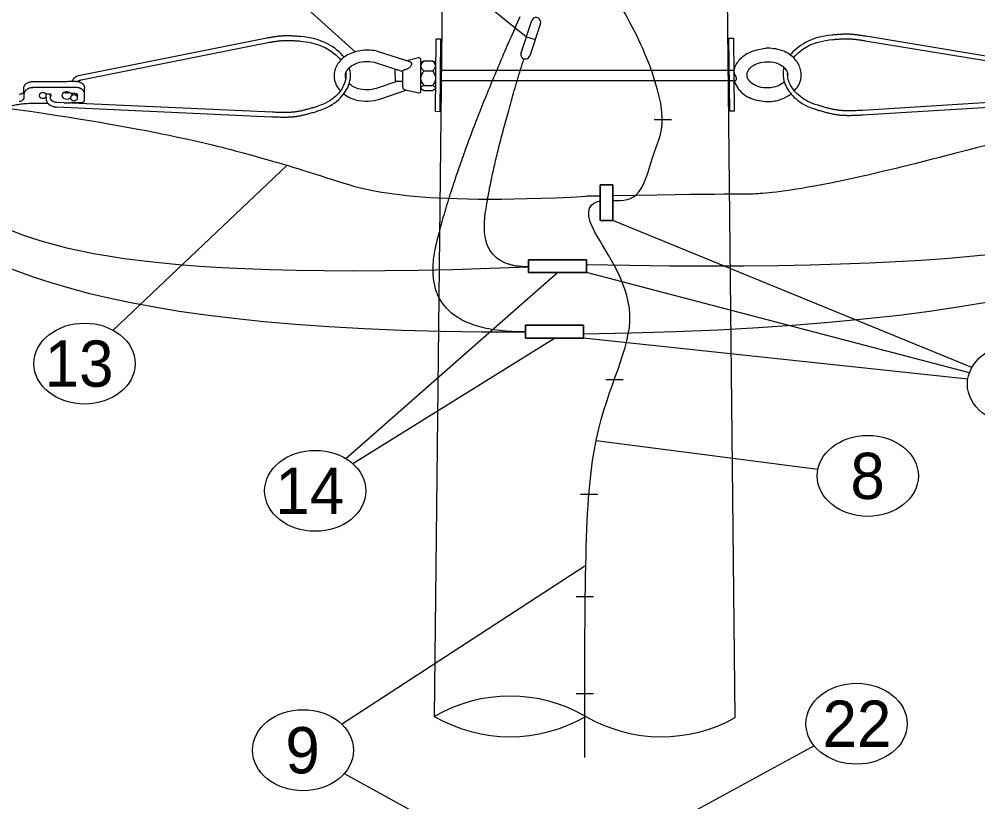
# Model space of a CAD drawing. Extents: x 99862 to 104211, y 98939 to 102076.
# Drawn here: x 101674.9 to 102006.5, y 101094.6 to 101365.3 of the extents above; entities that cross this region are included whole.
import ezdxf

# ---------------------------------------------------------------- set-up
doc = ezdxf.new("R2010")
doc.units = 0
for name, color, linetype in [('Level 1', 7, 'Continuous'), ('Level 11', 7, 'Continuous'), ('Level 12', 7, 'Continuous'), ('Level 13', 7, 'Continuous'), ('Level 15', 7, 'Continuous'), ('Level 16', 7, 'Continuous'), ('Level 17', 7, 'Continuous'), ('Level 20', 7, 'Continuous'), ('Level 40', 7, 'Continuous'), ('Level 5', 7, 'Continuous'), ('Level 6', 7, 'Continuous')]:
    doc.layers.add(name, color=color, linetype=linetype)

msp = doc.modelspace()

# ---------------------------------------------------------------- linework, layer by layer
at = {"layer": 'Level 1'}
for p, q in [((101822.66, 101507.01), (101818.5, 101124.11)), ((101922.64, 101123.74), (101918.48, 101507.01))]:
    msp.add_line(p, q, dxfattribs=at)
for centre, start, end in [((101844.7, 101078.73), 60, 120), ((101844.7, 101169.49), 240, 300), ((101897.1, 101169.49), 240, 299.1652)]:
    msp.add_arc(centre, 52.4, start, end, dxfattribs=at)
at = {"layer": 'Level 11'}
for p, q in [((101894.6, 101330.58), (101900.6, 101330.58)), ((101877.88, 101240.67), (101883.88, 101240.67)), ((101869.05, 101201.02), (101875.05, 101201.02)), ((101867.57, 101165.56), (101873.57, 101165.56)), ((101867.57, 101131.99), (101873.57, 101131.99))]:
    msp.add_line(p, q, dxfattribs=at)
for points, degree in [([(101880.31, 101302.54), (101883.77, 101302.51), (101890.12, 101302.55), (101894.49, 101320.44), (101899.51, 101330.05), (101891.01, 101357.11), (101876.44, 101380.43), (101871.67, 101395.71), (101871.77, 101403.52)], 3), ([(101850, 101257.11), (101811.89, 101257.11), (101826.6, 101318.15), (101848.24, 101366.2)], 2), ([(101851.09, 101279.6), (101833.87, 101279.6), (101838.28, 101315.06), (101849.48, 101351.62)], 2), ([(101870.57, 101109.85), (101870.57, 101176.15), (101870.57, 101226.43), (101894.7, 101263.78), (101867.64, 101297.44), (101872.7, 101301.79), (101875.86, 101302.4)], 3)]:
    msp.add_open_spline(points, degree=degree, dxfattribs=at)
at = {"layer": 'Level 12'}
for points, degree in [([(101664.3, 101335.46), (101718.51, 101328.04), (101761.77, 101316.71), (101778.05, 101311.49), (101811.01, 101300.81), (101871.2, 101304.04)], 3), ([(102062.44, 101335.69), (101998.25, 101318.55), (101954.14, 101307.33), (101926.64, 101304.24), (101926.64, 101304.98), (101880.31, 101304.22)], 3), ([(101875.86, 101304.13), (101874.35, 101304.1), (101872.8, 101304.07), (101871.2, 101304.04)], 2)]:
    msp.add_open_spline(points, degree=degree, dxfattribs=at)
at = {"layer": 'Level 13'}
for p, q in [((101697.5, 101339.42), (101697.47, 101341.54)), ((101681.79, 101338.86), (101681.79, 101338.86)), ((101685.25, 101339.38), (101684.16, 101339.37)), ((101685.28, 101339.38), (101685.25, 101339.38)), ((101689.62, 101338.9), (101689.62, 101338.9)), ((101694.27, 101339.59), (101692.78, 101339.58))]:
    msp.add_line(p, q, dxfattribs=at)
for centre, major_axis, start_param, end_param in [((101683.07, 101338.88), (-1.28, -0.01), 3.682555, 8.848759), ((101691.32, 101338.92), (-1.71, -0.02), 3.682555, 8.831964), ((101691.3, 101341.04), (1.71, 0.02), 4.155415, 5.269363), ((101685.28, 101338.89), (-0.669, -0.008), 2.263509, 4.704116), ((101694.27, 101338.93), (-0.891, -0.01), 2.333521, 4.704116)]:
    msp.add_ellipse(centre, major_axis=major_axis, ratio=0.733102, start_param=start_param, end_param=end_param, dxfattribs=at)
for points, degree in [([(101674.83, 101339.44), (101675.14, 101339.38), (101675.45, 101339.39), (101675.99, 101339.57), (101676.21, 101339.73), (101676.41, 101340.03), (101676.45, 101340.13), (101676.49, 101340.36), (101676.48, 101340.48), (101676.48, 101340.83), (101676.48, 101341.06), (101676.48, 101341.41), (101676.48, 101341.53), (101676.5, 101341.75), (101676.52, 101341.87), (101676.59, 101342.09), (101676.64, 101342.2), (101676.76, 101342.41), (101676.83, 101342.51), (101677.07, 101342.8), (101677.27, 101342.98), (101677.74, 101343.28), (101678.01, 101343.4), (101678.3, 101343.51)], 3), ([(101678.3, 101343.51), (101678.53, 101343.58), (101678.76, 101343.64), (101679.12, 101343.69), (101679.24, 101343.71), (101679.48, 101343.72), (101680.1, 101343.72), (101681.69, 101343.73), (101685.13, 101343.75), (101689.06, 101343.77), (101692.26, 101343.79), (101693.61, 101343.8), (101693.97, 101343.8), (101694.22, 101343.8), (101694.59, 101343.81), (101694.95, 101343.77), (101695.43, 101343.67), (101695.67, 101343.6), (101696.1, 101343.42), (101696.31, 101343.31), (101696.67, 101343.06), (101696.83, 101342.92), (101697.11, 101342.62), (101697.22, 101342.45), (101697.38, 101342.11), (101697.44, 101341.92), (101697.47, 101341.67), (101697.47, 101341.59), (101697.47, 101341.52)], 3), ([(101678.33, 101341.38), (101678.04, 101341.28), (101677.77, 101341.15), (101677.3, 101340.81), (101677.1, 101340.62), (101676.86, 101340.3), (101676.79, 101340.19), (101676.67, 101339.97), (101676.62, 101339.85), (101676.55, 101339.62), (101676.53, 101339.5), (101676.51, 101339.27), (101676.51, 101339.15), (101676.51, 101338.8), (101676.51, 101338.57), (101676.51, 101338.22), (101676.52, 101338.1), (101676.48, 101337.87), (101676.35, 101337.52), (101676.02, 101337.22), (101675.48, 101336.92), (101675.17, 101336.82), (101674.86, 101336.78)], 3), ([(101697.5, 101337.43), (101697.5, 101337.8), (101697.5, 101338.34), (101697.5, 101338.98), (101697.5, 101339.25), (101697.5, 101339.44), (101697.5, 101339.53), (101697.46, 101339.8), (101697.41, 101339.98), (101697.24, 101340.32), (101697.14, 101340.48), (101696.87, 101340.79), (101696.71, 101340.93), (101696.35, 101341.18), (101696.15, 101341.29), (101695.72, 101341.47), (101695.49, 101341.54), (101695.01, 101341.64), (101694.76, 101341.66), (101694.4, 101341.68), (101694.27, 101341.67), (101694.03, 101341.67), (101693.66, 101341.67), (101692.31, 101341.66), (101689.11, 101341.65), (101685.18, 101341.63), (101681.74, 101341.61), (101680.26, 101341.6), (101679.65, 101341.6), (101679.53, 101341.6), (101679.28, 101341.58), (101679.16, 101341.57), (101678.79, 101341.52), (101678.55, 101341.46), (101678.33, 101341.38)], 3), ([(101696.83, 101336.49), (101696.89, 101336.52), (101696.96, 101336.56), (101697.17, 101336.71), (101697.29, 101336.84), (101697.45, 101337.12), (101697.5, 101337.28), (101697.5, 101337.43)], 3), ([(101671.26, 101335), (101672.81, 101335.5), (101673.87, 101335.75), (101676.06, 101336.09), (101677.19, 101336.18), (101678.33, 101336.19)], 3), ([(101678.33, 101336.19), (101679.61, 101336.19), (101680.9, 101336.2), (101684.75, 101336.26)], 2), ([(101690.43, 101336.36), (101692.24, 101336.4), (101694.35, 101336.44), (101696.83, 101336.49)], 2)]:
    msp.add_open_spline(points, degree=degree, dxfattribs=at)
at = {"layer": 'Level 15'}
for p, q in [((101787.04, 101410.1), (101850.38, 101359.23)), ((101763.3, 101379.1), (101791.07, 101353.99)), ((101760.58, 101358.73), (101696, 101345.81)), ((101696.27, 101344.27), (101760.85, 101357.19)), ((101967.54, 101357.83), (102041.4, 101345.63)), ((102041.66, 101347.17), (101967.8, 101359.37)), ((101684.14, 101339.4), (101684.14, 101338.87)), ((101684.14, 101338.87), (101684.15, 101337.79)), ((101685.7, 101338.89), (101685.7, 101339.27)), ((101685.72, 101337.81), (101685.7, 101338.89)), ((101693.05, 101339.58), (101693.06, 101338.87)), ((101694.62, 101338.89), (101694.61, 101339.54)), ((102032.83, 101337.85), (101966.59, 101333.75)), ((101687.78, 101334.92), (101762.29, 101331.56)), ((101762.37, 101333.12), (101687.86, 101336.48)), ((101966.68, 101332.19), (102032.93, 101336.29)), ((101767.43, 101314.73), (101707.43, 101257.66)), ((102004.46, 101244.77), (101880.31, 101295.67)), ((101787.86, 101213.3), (101861.15, 101277.64)), ((102003.63, 101242.96), (101871.2, 101277.64)), ((101790.26, 101211.55), (101860.05, 101254.99)), ((102003.07, 101240.73), (101870.11, 101254.99)), ((101951.2, 101209.54), (101874.45, 101219.44)), ((101786.44, 101121.44), (101870.57, 101176.15)), ((101949.92, 101113.96), (101874.19, 101072.68)), ((101787.34, 101104.32), (101867.72, 101060.33))]:
    msp.add_line(p, q, dxfattribs=at)
msp.add_circle((101693.85, 101338.09), 1.11, dxfattribs=at)
for centre, major_axis, ratio, start_param, end_param in [((101956.28, 101359.02), (-0.069, 0.778), 0.094229, 6.283185, 6.283199), ((101760.72, 101357.96), (-0.136, 0.769), 0.183912, 0, 0.000013), ((101772.1, 101358.5), (-0.06, -0.779), 0.083059, 3.141578, 3.141594), ((101967.67, 101358.6), (-0.127, -0.771), 0.172997, 3.141579, 3.141595)]:
    msp.add_ellipse(centre, major_axis=major_axis, ratio=ratio, start_param=start_param, end_param=end_param, dxfattribs=at)
for points, degree in [([(101956.21, 101359.8), (101952.45, 101359.47), (101946.65, 101357.69), (101942.73, 101354.34), (101941.6, 101352.93)], 3), ([(101967.8, 101359.37), (101964.02, 101359.99), (101960.07, 101360.14), (101956.21, 101359.8)], 2), ([(101772.16, 101359.28), (101768.29, 101359.58), (101764.35, 101359.39), (101760.58, 101358.73)], 2), ([(101760.85, 101357.19), (101764.49, 101357.83), (101768.3, 101358.01), (101772.04, 101357.72)], 2), ([(101772.04, 101357.72), (101774.96, 101357.49), (101779.54, 101356.33), (101783.94, 101353.55), (101785.57, 101351.82), (101786.11, 101351.07)], 3), ([(101787.28, 101352.1), (101786.01, 101353.79), (101781.85, 101357.27), (101775.76, 101359), (101772.16, 101359.28)], 3), ([(101942.8, 101351.95), (101942.98, 101352.17), (101944.05, 101353.43), (101947.77, 101356.38), (101952.84, 101357.94), (101956.35, 101358.24)], 3), ([(101956.35, 101358.24), (101960.08, 101358.57), (101963.89, 101358.43), (101967.54, 101357.83)], 2), ([(101787.89, 101346.72), (101788.03, 101345.48), (101787.73, 101343.04), (101784.99, 101338.57), (101780.86, 101336.04), (101777.67, 101335.02)], 3), ([(101778.14, 101333.53), (101781.59, 101334.63), (101786.03, 101337.33), (101789.1, 101342.23), (101789.68, 101345.69), (101789.33, 101347.78), (101789.11, 101348.54)], 3), ([(101939.44, 101348.67), (101939.24, 101347.85), (101938.99, 101345.69), (101939.8, 101342.22), (101943.09, 101337.53), (101947.48, 101335), (101950.79, 101333.99)], 3), ([(101951.25, 101335.49), (101948.57, 101336.3), (101944.75, 101338.35), (101941.37, 101342.44), (101940.7, 101345.07), (101940.73, 101346.52)], 3), ([(101696, 101345.81), (101694.85, 101345.61), (101693.69, 101344.93), (101693.21, 101343.92), (101693.16, 101343.79)], 3), ([(101695.11, 101343.8), (101695.4, 101344.01), (101695.81, 101344.19), (101696.27, 101344.27)], 2), ([(101684.15, 101337.79), (101684.16, 101337.21), (101684.81, 101335.71), (101686.61, 101334.98), (101687.78, 101334.92)], 3), ([(101687.86, 101336.48), (101687.3, 101336.51), (101686.45, 101336.77), (101685.8, 101337.38), (101685.72, 101337.67), (101685.72, 101337.81)], 3), ([(101762.29, 101331.56), (101767.7, 101331.28), (101773.21, 101331.97), (101778.14, 101333.53)], 2), ([(101777.67, 101335.02), (101772.93, 101333.51), (101767.6, 101332.85), (101762.37, 101333.12)], 2), ([(101950.79, 101333.99), (101955.75, 101332.48), (101961.28, 101331.86), (101966.68, 101332.19)], 2), ([(101966.59, 101333.75), (101961.36, 101333.42), (101956.02, 101334.03), (101951.25, 101335.49)], 2)]:
    msp.add_open_spline(points, degree=degree, dxfattribs=at)
at = {"layer": 'Level 16'}
for points in [[(102150.05, 101341.31), (102144.38, 101338.07), (102118.28, 101319.1), (102049, 101258.95), (101870.11, 101256.31)], [(102142.43, 101341.27), (102126.79, 101335.17), (102087.07, 101304.71), (102032.13, 101277.19), (101871.2, 101280.29)], [(101584.53, 101338.96), (101590.2, 101335.72), (101616.28, 101316.78), (101685.63, 101256.57), (101850, 101257.11)], [(101592.05, 101338.93), (101607.71, 101332.86), (101648.17, 101301.81), (101704.43, 101273.82), (101851.09, 101279.6)]]:
    msp.add_open_spline(points, degree=3, dxfattribs=at)
at = {"layer": 'Level 17'}
for p, q in [((101848.54, 101353.68), (101852.23, 101364.79)), ((101855.22, 101363.79), (101851.51, 101352.62)), ((101850.38, 101359.23), (101853.37, 101358.21))]:
    msp.add_line(p, q, dxfattribs=at)
for points in [[(101875.86, 101308.01), (101875.86, 101295.67), (101878.08, 101295.67), (101880.31, 101295.67), (101880.31, 101308.01), (101878.51, 101308.01)], [(101880.31, 101308.01), (101880.31, 101295.67), (101875.86, 101295.67), (101875.86, 101308.01)], [(101851.09, 101277.64), (101871.2, 101277.64), (101871.2, 101280.29), (101871.2, 101282.09), (101851.09, 101282.09), (101851.09, 101280.29)], [(101851.09, 101282.09), (101871.2, 101282.09), (101871.2, 101277.64), (101851.09, 101277.64)], [(101850, 101254.99), (101870.11, 101254.99), (101870.11, 101257.63), (101870.11, 101259.44), (101850, 101259.44), (101850, 101257.63)], [(101850, 101259.44), (101870.11, 101259.44), (101870.11, 101254.99), (101850, 101254.99)]]:
    msp.add_lwpolyline(points, close=True, dxfattribs=at)
for centre, start, end in [((101853.73, 101364.29), 341.6062, 161.6358), ((101850.01, 101353.1), 158.5454, 342.2262)]:
    msp.add_arc(centre, 1.58, start, end, dxfattribs=at)
at = {"layer": 'Level 20'}
for centre in [(101697.48, 101246.15), (102020.44, 101239.07), (101968.47, 101207.31), (101777.3, 101202.14), (101964.59, 101121.59), (101773.06, 101112.42)]:
    msp.add_ellipse(centre, major_axis=(-17.5, 0), ratio=0.8, dxfattribs=at)
at = {"layer": 'Level 40'}
for p, q in [((101814.21, 101350.49), (101813.94, 101350.31)), ((101814.89, 101350.84), (101817.88, 101350.84)), ((101818.91, 101350.26), (101818.56, 101350.49)), ((101818.91, 101350.26), (101818.91, 101349.29)), ((101814.89, 101347.4), (101817.88, 101347.4)), ((101818.91, 101349.29), (101818.91, 101348.94)), ((101818.91, 101348.94), (101818.91, 101345.12)), ((101818.91, 101345.12), (101818.91, 101344.6)), ((101818.91, 101344.6), (101818.91, 101341.58)), ((101814.89, 101342.32), (101817.88, 101342.32)), ((101814.89, 101340.67), (101817.88, 101340.67)), ((101818.56, 101341.02), (101818.56, 101341.02)), ((101818.91, 101341.58), (101818.91, 101341.41))]:
    msp.add_line(p, q, dxfattribs=at)
for points, degree in [([(101814.89, 101350.84), (101814.63, 101350.61), (101814.4, 101350.37), (101814.03, 101349.86), (101813.9, 101349.58), (101813.86, 101349.29)], 3), ([(101814.21, 101350.49), (101814.4, 101350.61), (101814.63, 101350.73), (101814.89, 101350.84)], 2), ([(101817.88, 101350.84), (101818.14, 101350.73), (101818.37, 101350.62), (101818.56, 101350.49)], 2), ([(101818.91, 101349.29), (101818.87, 101349.58), (101818.74, 101349.85), (101818.37, 101350.37), (101818.14, 101350.61), (101817.88, 101350.84)], 3), ([(101813.86, 101348.94), (101813.9, 101348.66), (101814.03, 101348.38), (101814.4, 101347.87), (101814.63, 101347.63), (101814.89, 101347.4)], 3), ([(101814.89, 101347.4), (101814.63, 101347.06), (101814.4, 101346.7), (101814.05, 101345.99), (101813.93, 101345.63), (101813.88, 101345.27)], 3), ([(101817.88, 101347.4), (101818.14, 101347.63), (101818.37, 101347.87), (101818.74, 101348.38), (101818.87, 101348.66), (101818.91, 101348.94)], 3), ([(101817.88, 101347.4), (101818.14, 101347.06), (101818.37, 101346.7), (101818.74, 101345.95), (101818.87, 101345.54), (101818.91, 101345.12)], 3), ([(101813.88, 101344.43), (101813.93, 101344.07), (101814.05, 101343.72), (101814.4, 101343.01), (101814.63, 101342.65), (101814.89, 101342.32)], 3), ([(101818.91, 101344.6), (101818.87, 101344.18), (101818.74, 101343.77), (101818.37, 101343.01), (101818.14, 101342.65), (101817.88, 101342.32)], 3), ([(101814.89, 101342.32), (101814.63, 101342.21), (101814.4, 101342.09), (101814.06, 101341.87), (101813.95, 101341.76), (101813.89, 101341.65)], 3), ([(101813.93, 101341.27), (101814, 101341.18), (101814.09, 101341.1), (101814.4, 101340.9), (101814.63, 101340.78), (101814.89, 101340.67)], 3), ([(101818.91, 101341.58), (101818.87, 101341.72), (101818.74, 101341.85), (101818.37, 101342.09), (101818.14, 101342.21), (101817.88, 101342.32)], 3), ([(101817.88, 101340.67), (101818.14, 101340.78), (101818.37, 101340.9), (101818.74, 101341.14), (101818.87, 101341.27), (101818.91, 101341.41)], 3)]:
    msp.add_open_spline(points, degree=degree, dxfattribs=at)
at = {"layer": 'Level 5'}
for p, q in [((101805.86, 101347.77), (101804.89, 101347.77)), ((101804.89, 101347.77), (101804.91, 101343.86)), ((101820.6, 101347.66), (101922.3, 101347.66)), ((101804.91, 101343.86), (101807.6, 101343.87)), ((101820.57, 101344.1), (101922.75, 101344.1))]:
    msp.add_line(p, q, dxfattribs=at)
for points in [[(101922.2, 101347.11), (101922.42, 101348.6), (101923.02, 101350.03), (101926.3, 101353.86), (101930.7, 101354.95), (101933.22, 101355.23)], [(101943.06, 101340.49), (101943.44, 101340.88), (101944.57, 101342.27), (101945.66, 101345.03), (101945.29, 101348.64), (101942.95, 101352.37), (101938.73, 101354.78), (101935.13, 101355.27), (101933.22, 101355.23)], [(101939.57, 101343.62), (101938.99, 101343.06), (101937.38, 101342.02), (101934.09, 101341.34), (101930.7, 101341.76), (101928.46, 101342.92), (101927.09, 101344.34), (101926.63, 101345.55), (101926.74, 101346.74), (101927.2, 101347.74), (101928.3, 101348.98), (101930.46, 101350.21), (101932.66, 101350.57), (101933.74, 101350.57)], [(101933.74, 101350.57), (101935.28, 101350.58), (101937.93, 101349.97), (101939.94, 101348.33), (101940.69, 101346.97), (101940.79, 101346.25), (101940.74, 101345.82)], [(101922.56, 101344.04), (101922.67, 101344.05), (101922.79, 101344.1), (101922.94, 101344.26), (101922.99, 101344.32), (101923.05, 101344.47), (101923.07, 101344.56), (101923.07, 101344.86), (101922.99, 101345.09), (101922.79, 101345.56), (101922.67, 101345.8), (101922.45, 101346.29), (101922.36, 101346.54), (101922.25, 101346.89), (101922.22, 101347.01), (101922.18, 101347.22), (101922.17, 101347.32), (101922.17, 101347.58), (101922.2, 101347.72), (101922.26, 101347.8)], [(101922.27, 101344.03), (101922.73, 101342.37), (101924.89, 101339.22), (101930.03, 101336.91), (101936.02, 101336.66), (101939.81, 101337.95), (101941.69, 101339.29), (101941.9, 101339.45)]]:
    msp.add_open_spline(points, degree=3, dxfattribs=at)
at = {"layer": 'Level 6'}
for p, q in [((101810.14, 101350.49), (101799.58, 101353.91)), ((101798.38, 101350.19), (101807.6, 101347.21)), ((101813.03, 101351.91), (101808.97, 101350.87)), ((101805.84, 101343.86), (101798.36, 101341.36)), ((101799.6, 101337.66), (101809, 101340.8)), ((101808.09, 101341.02), (101813.1, 101339.8))]:
    msp.add_line(p, q, dxfattribs=at)
for points in [[(101820.44, 101333.29), (101818.89, 101333.3), (101819.12, 101358.49), (101820.67, 101358.48)], [(101922.22, 101333.51), (101920.7, 101333.5), (101920.45, 101358.69), (101921.97, 101358.71)]]:
    msp.add_lwpolyline(points, close=True, dxfattribs=at)
for centre, major_axis, ratio, start_param, end_param in [((101813.07, 101345.85), (-0.03, 6.06), 0.005627, 0.000007, 0.001411), ((101813.84, 101345.86), (0.03, -5.45), 0.005627, 0.127046, 3.065713), ((101807.59, 101345.83), (-0.01, 1.95), 0.005627, 3.141582, 5.497196), ((101807.59, 101349.26), (0.01, -2.06), 0.005565, 6.281347, 6.726256), ((101807.59, 101342.39), (0.01, -2.06), 0.005565, 1.293805, 2.376637)]:
    msp.add_ellipse(centre, major_axis=major_axis, ratio=ratio, start_param=start_param, end_param=end_param, dxfattribs=at)
for points in [[(101799.58, 101353.91), (101797.74, 101354.51), (101794.2, 101354.86), (101788.76, 101353.46), (101785.07, 101350.52), (101783.58, 101346.56), (101784.02, 101343.17), (101785.26, 101341.27), (101786.02, 101340.47)], [(101787.87, 101344.77), (101787.78, 101345.06), (101787.67, 101345.71), (101787.87, 101347.04), (101789.07, 101348.8), (101791.87, 101350.34), (101795.25, 101350.85), (101797.44, 101350.5), (101798.38, 101350.19)], [(101810.14, 101350.49), (101810.24, 101350.46), (101810.33, 101350.41), (101810.49, 101350.3), (101810.55, 101350.22), (101810.63, 101350.05), (101810.65, 101349.95), (101810.66, 101349.63), (101810.58, 101349.37), (101810.28, 101348.88), (101810.06, 101348.65), (101809.56, 101348.26), (101809.28, 101348.1), (101808.69, 101347.86), (101808.39, 101347.78), (101808.08, 101347.72)], [(101813.82, 101351.29), (101813.82, 101351.31), (101813.81, 101351.34), (101813.81, 101351.38), (101813.77, 101351.56), (101813.57, 101351.87), (101813.25, 101351.97), (101813.03, 101351.91)], [(101807.61, 101347.41), (101807.61, 101347.46), (101807.65, 101347.53), (101807.83, 101347.64), (101807.94, 101347.7), (101808.08, 101347.72)], [(101798.36, 101341.36), (101797.46, 101341.06), (101795.31, 101340.68), (101791.97, 101341.11), (101789.95, 101342.16), (101789.17, 101342.84), (101789.06, 101342.95)], [(101807.61, 101341.82), (101807.61, 101341.71), (101807.61, 101341.65), (101807.62, 101341.57), (101807.63, 101341.44), (101807.76, 101341.19), (101807.94, 101341.06), (101808.09, 101341.02)], [(101813.09, 101339.8), (101813.34, 101339.73), (101813.67, 101339.86), (101813.84, 101340.19), (101813.87, 101340.32), (101813.87, 101340.39), (101813.88, 101340.42), (101813.87, 101340.45)], [(101787.19, 101339.42), (101788.43, 101338.48), (101791.22, 101337.18), (101795.72, 101336.76), (101798.42, 101337.26), (101799.6, 101337.66)]]:
    msp.add_open_spline(points, degree=3, dxfattribs=at)

# ---------------------------------------------------------------- texts
at = {"layer": 'Level 20'}
for s, p in [('13', (101683.7, 101238.15)), ('8', (101962.46, 101199.31)), ('14', (101763.52, 101194.14)), ('22', (101952.83, 101113.59)), ('9', (101766.97, 101104.42))]:
    msp.add_text(s, height=16, dxfattribs=at).set_placement(p)

doc.saveas('drawing.dxf')
